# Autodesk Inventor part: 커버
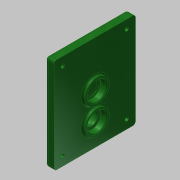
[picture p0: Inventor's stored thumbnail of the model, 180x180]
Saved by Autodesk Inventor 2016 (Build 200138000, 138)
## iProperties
Created: 2016-02
Part Number: 커버
Material: 일반
Document SubType Name: Modeling
Designer: mduedu
Density: 1 g/cm^3
Appearance: 매끄러움 - 짙은 산림 녹색
Mass: 100.463 g
Surface Area: 266.629 cm^2
Volume: 100.463 cm^3
Author: mduedu
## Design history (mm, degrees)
sketch "스케치1"
  geometry: L1 (63, 47)-(-47, 47); L2 (-47, 47)-(-47, -47); L3 (-47, -47)-(63, -47); L4 (63, -47)-(63, 47); 2 further points
  constraints: 8 end point, 2 parallel, 1 horizontal, 1 horizontal alignment, 1 midpoint, 1 perpendicular
  dimensions: "d102" = 94 distance of L3.end L1.start; "d104" = 47 distance from line of L2 point (0, 0); "d105" = 110 distance of L1.start L1.end
extrude "돌출1" new body sketch "스케치1" distance "d1" = 10; taper "d2" = 0 deg
sketch "스케치2"
  geometry: C1 r 14 at (0, 11); 1 further point
  constraints: 1 centre point, 1 vertical alignment
  dimensions: "d3" = 28 diameter of C1; "d6" = 11 distance of C1.centre point (0, 0)
extrude "돌출2" join sketch "스케치2" distance "d7" = 3; taper "d8" = 0 deg
sketch "스케치3"
  geometry: C1 r 14 at (0, -20); 1 further point
  constraints: 1 centre point, 1 vertical alignment
  dimensions: "d9" = 28 diameter of C1; "d10" = 20 distance of C1.centre point (0, 0)
extrude "돌출3" join sketch "스케치3" distance "d11" = 3; taper "d12" = 0 deg
hole "구멍1" diameter "d15" = 22; stored, may be unused: countersink angle "d19" = 90 deg, drill point angle "d21" = 0 deg; dims "d13" = 10, "d14" = 10, "d16" = 6, "d17" = 4, "d18" = 2, "d20" = 7
hole "구멍2" diameter "d24" = 18; stored, may be unused: countersink angle "d28" = 90 deg, drill point angle "d30" = 0 deg; dims "d22" = 10, "d23" = 10, "d25" = 6, "d26" = 4, "d27" = 2, "d29" = 1
hole "구멍3" diameter "d33" = 22; stored, may be unused: countersink angle "d37" = 90 deg, drill point angle "d39" = 0 deg; dims "d34" = 6, "d35" = 4, "d36" = 2, "d38" = 7, "d73" = 10, "d74" = 10
sketch "스케치4"
  geometry: C1 r 14 at (0, -20) reference; C2 r 18 at (0, -20); 1 further point
  constraints: 1 centre point, 1 coincident
  dimensions: "d40" = 36 diameter of C2
extrude "돌출4" join sketch "스케치4" distance "d41" = 4; taper "d42" = 0 deg
hole "구멍4" diameter "d45" = 22; stored, may be unused: countersink angle "d49" = 90 deg, drill point angle "d51" = 0 deg; dims "d43" = 10, "d44" = 10, "d46" = 6, "d47" = 4, "d48" = 2, "d50" = 7
hole "구멍5" diameter "d54" = 15; stored, may be unused: countersink angle "d58" = 90 deg, drill point angle "d60" = 0 deg; dims "d52" = 10, "d53" = 10, "d55" = 6, "d56" = 4, "d57" = 2, "d59" = 7
fillet "모깎기1" dims "d61" = 0.3
fillet "모깎기2" dims "d62" = 2
chamfer "모따기1" distance "d63" = 1; stored, may be unused: second distance "d64" = 2, angle "d65" = 45 deg
fillet "모깎기6" dims "d88" = 2
fillet "모깎기4" dims "d75" = 2
sketch "스케치9"
  geometry: L1 (47, 63)-(47, -47) reference; L2 (-47, 63)-(47, 63) reference; L3 (-47, -47)-(-47, 63) reference; L4 (47, -47)-(-47, -47) reference; L5 (37, 53)-(37, -37); L6 (37, -37)-(-37, -37); L7 (-37, -37)-(-37, 53); L8 (-37, 53)-(37, 53); C1 r 20 at (0, -20) reference; 5 further points
  constraints: 8 end point, 4 coincident, 3 other
  dimensions: "d107" = 10 distance between parallel lines of L8 L2
hole "구멍7" sketch "스케치9" at (-37, 53), (37, 53), (37, -37), (-37, -37) diameter "d108" = 4.5; stored, may be unused: countersink angle "d112" = 90 deg, drill point angle "d114" = 118 deg; dims "d109" = 6, "d110" = 8, "d111" = 4.6, "d113" = 8
fillet "모깎기8" dims "d106" = 3
fillet "모깎기9" dims "d115" = 3
node "솔리드1"
node "투영된 루프2"
